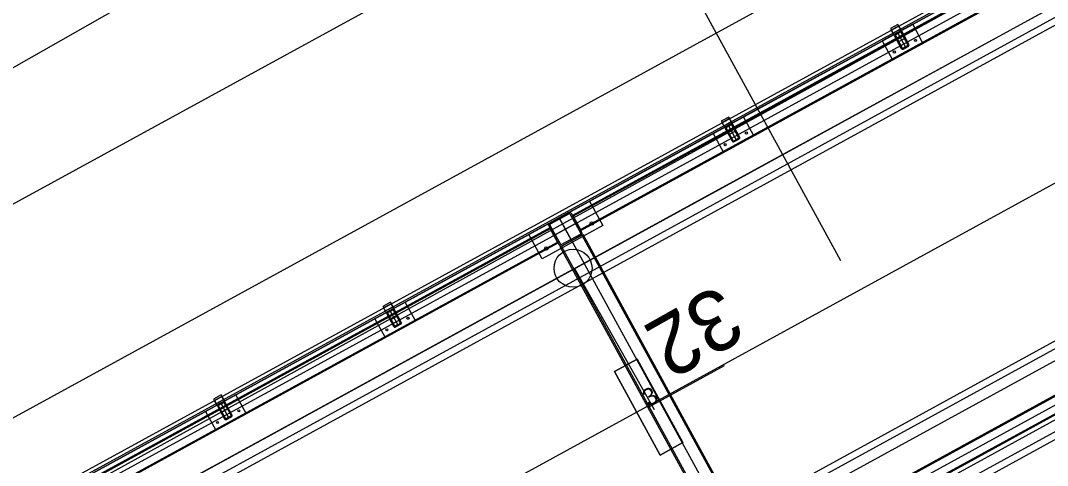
# Model space of a CAD drawing. Extents: x -783978 to -783565, y -1064821 to -1064596.
# Drawn here: x -783747.19 to -783741.25, y -1064670.72 to -1064668.14 of the extents above; entities that cross this region are included whole.
import ezdxf

# ---------------------------------------------------------------- set-up
doc = ezdxf.new("R2010")
doc.units = 0
for name, color, linetype in [('Default', 7, 'Continuous'), ('SO 01_11_01', 7, 'Continuous'), ('SO 01_20_01', 7, 'Continuous'), ('SO 01_50_01', 7, 'Continuous'), ('SO 01_74_01', 7, 'Continuous'), ('SO 01_86_04', 7, 'Continuous')]:
    doc.layers.add(name, color=color, linetype=linetype)

# ---------------------------------------------------------------- blocks, each defined once
blk = doc.blocks.new('POINT_DISPLAY')
at = {"layer": 'Default'}
blk.add_line((0, 0), (0, 0), dxfattribs=at)

msp = doc.modelspace()

# ---------------------------------------------------------------- linework, layer by layer
at = {"layer": 'SO 01_11_01'}
for p, q in [((-783772.8819, -1064683.2217), (-783730.898, -1064660.279)), ((-783749.059, -1064669.4549), (-783743.8421, -1064666.4911))]:
    msp.add_line(p, q, dxfattribs=at)
at = {"layer": 'SO 01_20_01'}
for p, q in [((-783735.0054, -1064663.7532), (-783787.4671, -1064692.4555)), ((-783735.2041, -1064664.4318), (-783786.7885, -1064692.6541)), ((-783786.6445, -1064692.9173), (-783735.3233, -1064664.839)), ((-783738.0171, -1064666.3812), (-783786.4402, -1064692.874)), ((-783786.421, -1064692.9091), (-783737.9979, -1064666.4163)), ((-783737.8741, -1064667.2605), (-783785.3352, -1064693.2269)), ((-783785.6531, -1064694.3127), (-783737.23, -1064667.82)), ((-783737.0912, -1064667.858), (-783785.7805, -1064694.4964)), ((-783737.2108, -1064667.855), (-783785.6339, -1064694.3478)), ((-783785.6366, -1064694.7596), (-783736.9472, -1064668.1212)), ((-783737.0092, -1064668.2235), (-783746.0685, -1064673.1799)), ((-783746.0493, -1064673.215), (-783736.99, -1064668.2586))]:
    msp.add_line(p, q, dxfattribs=at)
at = {"layer": 'SO 01_50_01'}
for p, q in [((-783786.7885, -1064692.6541), (-783725.4827, -1064659.1131)), ((-783742.9243, -1064668.6556), (-783738.5378, -1064666.2557)), ((-783742.9242, -1064668.6557), (-783738.5378, -1064666.2558)), ((-783742.9242, -1064668.6557), (-783738.5378, -1064666.2558)), ((-783742.4443, -1064669.5329), (-783743.4042, -1064667.7783)), ((-783747.3107, -1064671.0555), (-783742.9243, -1064668.6556)), ((-783747.3106, -1064671.0555), (-783742.9242, -1064668.6557)), ((-783747.3106, -1064671.0555), (-783742.9242, -1064668.6557))]:
    msp.add_line(p, q, dxfattribs=at)
at = {"layer": 'SO 01_74_01'}
for p, q in [((-783735.2185, -1064664.4055), (-783786.6099, -1064692.5222)), ((-783786.6003, -1064692.5398), (-783735.2089, -1064664.423)), ((-783741.1927, -1064667.7368), (-783743.9955, -1064669.2702)), ((-783741.1897, -1064667.7423), (-783743.9925, -1064669.2757)), ((-783743.9505, -1064669.3524), (-783741.1477, -1064667.819)), ((-783743.9475, -1064669.3579), (-783741.1447, -1064667.8245)), ((-783742.1144, -1064668.1669), (-783742.1582, -1064668.1909)), ((-783742.1582, -1064668.1909), (-783742.139, -1064668.226)), ((-783742.1096, -1064668.1757), (-783742.1534, -1064668.1997)), ((-783742.0952, -1064668.202), (-783742.1144, -1064668.1669)), ((-783742.1, -1064668.1932), (-783742.1096, -1064668.1757)), ((-783742.1534, -1064668.1997), (-783742.1438, -1064668.2172)), ((-783742.1438, -1064668.2172), (-783742.1, -1064668.1932)), ((-783742.139, -1064668.226), (-783742.0952, -1064668.202)), ((-783743.0925, -1064668.7021), (-783743.1364, -1064668.7261)), ((-783743.1364, -1064668.7261), (-783743.1172, -1064668.7612)), ((-783743.0877, -1064668.7108), (-783743.1316, -1064668.7348)), ((-783743.0733, -1064668.7372), (-783743.0925, -1064668.7021)), ((-783743.0781, -1064668.7284), (-783743.0877, -1064668.7108)), ((-783743.1316, -1064668.7348), (-783743.122, -1064668.7524)), ((-783743.122, -1064668.7524), (-783743.0781, -1064668.7284)), ((-783743.1172, -1064668.7612), (-783743.0733, -1064668.7372)), ((-783743.9955, -1064669.2702), (-783743.9475, -1064669.3579)), ((-783743.9925, -1064669.2757), (-783743.9505, -1064669.3524)), ((-783744.1272, -1064669.3423), (-783746.93, -1064670.8757)), ((-783744.1242, -1064669.3478), (-783746.927, -1064670.8812)), ((-783744.0792, -1064669.43), (-783744.1272, -1064669.3423)), ((-783744.0823, -1064669.4245), (-783744.1242, -1064669.3478)), ((-783746.8851, -1064670.9579), (-783744.0823, -1064669.4245)), ((-783746.882, -1064670.9634), (-783744.0792, -1064669.43)), ((-783744.0672, -1064669.4519), (-783743.9357, -1064669.3799)), ((-783744.0602, -1064669.4481), (-783743.9427, -1064669.3838)), ((-783743.9427, -1064669.3838), (-783741.9268, -1064673.0684)), ((-783743.9357, -1064669.3799), (-783741.9198, -1064673.0645)), ((-783742.0514, -1064673.1365), (-783744.0672, -1064669.4519)), ((-783742.0443, -1064673.1327), (-783744.0602, -1064669.4481)), ((-783740.1128, -1064669.7106), (-783742.9156, -1064671.2441)), ((-783740.1098, -1064669.7162), (-783742.9126, -1064671.2496)), ((-783745.0489, -1064669.7724), (-783745.0927, -1064669.7964)), ((-783745.0441, -1064669.7812), (-783745.0879, -1064669.8052)), ((-783745.0297, -1064669.8075), (-783745.0489, -1064669.7724)), ((-783745.0345, -1064669.7987), (-783745.0441, -1064669.7812)), ((-783742.8706, -1064671.3263), (-783740.0678, -1064669.7928)), ((-783745.0927, -1064669.7964), (-783745.0735, -1064669.8315)), ((-783745.0879, -1064669.8052), (-783745.0783, -1064669.8227)), ((-783745.0783, -1064669.8227), (-783745.0345, -1064669.7987)), ((-783745.0735, -1064669.8315), (-783745.0297, -1064669.8075)), ((-783742.8676, -1064671.3318), (-783740.0648, -1064669.7984)), ((-783746.0271, -1064670.3076), (-783746.0709, -1064670.3316)), ((-783746.0223, -1064670.3163), (-783746.0661, -1064670.3403)), ((-783746.0079, -1064670.3427), (-783746.0271, -1064670.3076)), ((-783746.0127, -1064670.3339), (-783746.0223, -1064670.3163)), ((-783746.0709, -1064670.3316), (-783746.0517, -1064670.3667)), ((-783746.0661, -1064670.3403), (-783746.0565, -1064670.3579)), ((-783746.0565, -1064670.3579), (-783746.0127, -1064670.3339)), ((-783746.0517, -1064670.3667), (-783746.0079, -1064670.3427))]:
    msp.add_line(p, q, dxfattribs=at)
for points in [[(-783735.1681, -1064664.4976), (-783787.4762, -1064693.1159)], [(-783734.0882, -1064666.4715), (-783786.3963, -1064695.0898)], [(-783742.1345, -1064668.2343), (-783742.0956, -1064668.3054)], [(-783742.1035, -1064668.2065), (-783742.1307, -1064668.2215)], [(-783742.129, -1064668.2313), (-783742.09, -1064668.3024)], [(-783742.1004, -1064668.2121), (-783742.1277, -1064668.227)], [(-783742.1171, -1064668.214), (-783742.0691, -1064668.3017)], [(-783742.0712, -1064668.2459), (-783742.115, -1064668.2699)], [(-783742.0572, -1064668.2845), (-783742.0962, -1064668.2133)], [(-783742.0517, -1064668.2814), (-783742.0906, -1064668.2103)], [(-783742.0858, -1064668.3037), (-783742.0585, -1064668.2887)], [(-783742.0827, -1064668.3092), (-783742.0555, -1064668.2943)], [(-783743.1127, -1064668.7694), (-783743.0737, -1064668.8406)], [(-783743.0816, -1064668.7417), (-783743.1089, -1064668.7566)], [(-783743.1071, -1064668.7664), (-783743.0682, -1064668.8376)], [(-783743.0786, -1064668.7472), (-783743.1059, -1064668.7621)], [(-783743.0953, -1064668.7492), (-783743.0473, -1064668.8369)], [(-783743.0493, -1064668.781), (-783743.0932, -1064668.805)], [(-783743.0354, -1064668.8196), (-783743.0743, -1064668.7485)], [(-783743.0299, -1064668.8166), (-783743.0688, -1064668.7454)], [(-783743.0639, -1064668.8388), (-783743.0367, -1064668.8239)], [(-783743.0609, -1064668.8444), (-783743.0336, -1064668.8294)], [(-783744.0182, -1064669.2541), (-783744.1287, -1064669.3146)], [(-783743.9414, -1064669.3694), (-783744.0019, -1064669.2589)], [(-783744.0143, -1064669.2611), (-783744.1249, -1064669.3216)], [(-783743.9716, -1064669.3141), (-783744.1032, -1064669.3861)], [(-783744.0734, -1064669.2843), (-783741.9136, -1064673.2321)], [(-783744.0014, -1064669.4159), (-783744.0734, -1064669.2843)], [(-783743.9484, -1064669.3732), (-783744.0089, -1064669.2627)], [(-783744.1335, -1064669.3309), (-783744.073, -1064669.4414)], [(-783744.1265, -1064669.327), (-783744.066, -1064669.4375)], [(-783744.0606, -1064669.4391), (-783743.95, -1064669.3787)], [(-783744.0567, -1064669.4462), (-783743.9462, -1064669.3857)], [(-783745.069, -1064669.8398), (-783745.0301, -1064669.9109)], [(-783745.038, -1064669.812), (-783745.0653, -1064669.827)], [(-783745.0635, -1064669.8368), (-783745.0246, -1064669.9079)], [(-783745.0349, -1064669.8176), (-783745.0622, -1064669.8325)], [(-783745.0516, -1064669.8195), (-783745.0036, -1064669.9072)], [(-783745.0057, -1064669.8514), (-783745.0495, -1064669.8754)], [(-783744.9917, -1064669.89), (-783745.0307, -1064669.8188)], [(-783744.9862, -1064669.8869), (-783745.0251, -1064669.8158)], [(-783745.0203, -1064669.9092), (-783744.993, -1064669.8942)], [(-783745.0173, -1064669.9147), (-783744.99, -1064669.8998)], [(-783746.0472, -1064670.375), (-783746.0083, -1064670.4461)], [(-783746.0161, -1064670.3472), (-783746.0434, -1064670.3621)], [(-783746.0417, -1064670.3719), (-783746.0027, -1064670.4431)], [(-783746.0131, -1064670.3527), (-783746.0404, -1064670.3677)], [(-783746.0298, -1064670.3547), (-783745.9818, -1064670.4424)], [(-783745.9839, -1064670.3865), (-783746.0277, -1064670.4105)], [(-783745.9699, -1064670.4251), (-783746.0088, -1064670.354)], [(-783745.9644, -1064670.4221), (-783746.0033, -1064670.351)], [(-783745.9985, -1064670.4443), (-783745.9712, -1064670.4294)], [(-783745.9954, -1064670.4499), (-783745.9681, -1064670.4349)]]:
    msp.add_lwpolyline(points, dxfattribs=at)
for points in [[(-783742.0294, -1064668.166), (-783742.2048, -1064668.262), (-783742.1472, -1064668.3673), (-783741.9718, -1064668.2713)], [(-783743.0075, -1064668.7012), (-783743.183, -1064668.7972), (-783743.1254, -1064668.9024), (-783742.9499, -1064668.8064)], [(-783743.8212, -1064669.3287), (-783744.1721, -1064669.5207), (-783744.2489, -1064669.3803), (-783743.898, -1064669.1883)], [(-783744.9639, -1064669.7715), (-783745.1393, -1064669.8675), (-783745.0817, -1064669.9728), (-783744.9063, -1064669.8768)], [(-783745.9421, -1064670.3067), (-783746.1175, -1064670.4027), (-783746.0599, -1064670.5079), (-783745.8845, -1064670.4119)]]:
    msp.add_lwpolyline(points, close=True, dxfattribs=at)
for centre, radius in [((-783742.0125, -1064668.2593), 0.006), ((-783742.1353, -1064668.3265), 0.006), ((-783742.9907, -1064668.7945), 0.006), ((-783743.1135, -1064668.8617), 0.006), ((-783743.8843, -1064669.3176), 0.01), ((-783744.1474, -1064669.4616), 0.01), ((-783744.947, -1064669.8649), 0.006), ((-783745.0698, -1064669.932), 0.006), ((-783745.9252, -1064670.4), 0.006), ((-783746.048, -1064670.4672), 0.006)]:
    msp.add_circle(centre, radius, dxfattribs=at)
for centre, radius, start, end in [((-783742.1262, -1064668.2297), 0.00945, 118.68349, 208.68349), ((-783742.1262, -1064668.2297), 0.00315, 118.68349, 208.68349), ((-783742.0989, -1064668.2148), 0.00945, 28.68349, 118.68349), ((-783742.0989, -1064668.2148), 0.00315, 28.68349, 118.68349), ((-783742.0873, -1064668.3009), 0.00945, 208.68349, 298.68349), ((-783742.0873, -1064668.3009), 0.00315, 208.68349, 298.68349), ((-783742.06, -1064668.286), 0.00315, 298.68349, 28.68349), ((-783742.06, -1064668.286), 0.00945, 298.68349, 28.68349), ((-783743.1044, -1064668.7649), 0.00945, 118.68349, 208.68349), ((-783743.1044, -1064668.7649), 0.00315, 118.68349, 208.68349), ((-783743.0771, -1064668.75), 0.00945, 28.68349, 118.68349), ((-783743.0771, -1064668.75), 0.00315, 28.68349, 118.68349), ((-783743.0655, -1064668.8361), 0.00945, 208.68349, 298.68349), ((-783743.0655, -1064668.8361), 0.00315, 208.68349, 298.68349), ((-783743.0382, -1064668.8211), 0.00315, 298.68349, 28.68349), ((-783743.0382, -1064668.8211), 0.00945, 298.68349, 28.68349), ((-783744.0124, -1064669.2646), 0.012, 28.68349, 118.68349), ((-783744.123, -1064669.3251), 0.012, 118.68349, 208.68349), ((-783744.0124, -1064669.2646), 0.004, 28.68349, 118.68349), ((-783744.123, -1064669.3251), 0.004, 118.68349, 208.68349), ((-783743.9519, -1064669.3752), 0.004, 298.68349, 28.68349), ((-783743.9519, -1064669.3752), 0.012, 298.68349, 28.68349), ((-783744.0625, -1064669.4356), 0.004, 208.68349, 298.68349), ((-783744.0625, -1064669.4356), 0.012, 208.68349, 298.68349), ((-783745.0607, -1064669.8352), 0.00945, 118.68349, 208.68349), ((-783745.0607, -1064669.8352), 0.00315, 118.68349, 208.68349), ((-783745.0334, -1064669.8203), 0.00945, 28.68349, 118.68349), ((-783745.0334, -1064669.8203), 0.00315, 28.68349, 118.68349), ((-783745.0218, -1064669.9064), 0.00945, 208.68349, 298.68349), ((-783745.0218, -1064669.9064), 0.00315, 208.68349, 298.68349), ((-783744.9945, -1064669.8915), 0.00315, 298.68349, 28.68349), ((-783744.9945, -1064669.8915), 0.00945, 298.68349, 28.68349), ((-783746.0389, -1064670.3704), 0.00945, 118.68349, 208.68349), ((-783746.0389, -1064670.3704), 0.00315, 118.68349, 208.68349), ((-783746.0116, -1064670.3555), 0.00945, 28.68349, 118.68349), ((-783746.0116, -1064670.3555), 0.00315, 28.68349, 118.68349), ((-783746, -1064670.4416), 0.00945, 208.68349, 298.68349), ((-783746, -1064670.4416), 0.00315, 208.68349, 298.68349), ((-783745.9727, -1064670.4266), 0.00315, 298.68349, 28.68349), ((-783745.9727, -1064670.4266), 0.00945, 298.68349, 28.68349)]:
    msp.add_arc(centre, radius, start, end, dxfattribs=at)
at = {"layer": 'SO 01_86_04'}
for p, q in [((-783743.9837, -1064669.5772), (-783743.5237, -1064670.3916)), ((-783743.6225, -1064670.1006), (-783743.7541, -1064670.1726)), ((-783743.6225, -1064670.1006), (-783743.7541, -1064670.1726)), ((-783743.7541, -1064670.1726), (-783743.6225, -1064670.1006)), ((-783743.7541, -1064670.1726), (-783743.6225, -1064670.1006)), ((-783743.3585, -1064670.5831), (-783743.6225, -1064670.1006)), ((-783743.3585, -1064670.5831), (-783743.6225, -1064670.1006)), ((-783743.6225, -1064670.1006), (-783743.3585, -1064670.5831)), ((-783743.6225, -1064670.1006), (-783743.3585, -1064670.5831)), ((-783743.5563, -1064670.3779), (-783743.1177, -1064670.1379)), ((-783743.7541, -1064670.1726), (-783743.4901, -1064670.6551)), ((-783743.7541, -1064670.1726), (-783743.4901, -1064670.6551)), ((-783743.4901, -1064670.6551), (-783743.7541, -1064670.1726)), ((-783743.4901, -1064670.6551), (-783743.7541, -1064670.1726)), ((-783743.4901, -1064670.6551), (-783743.3585, -1064670.5831)), ((-783743.4901, -1064670.6551), (-783743.3585, -1064670.5831)), ((-783743.3585, -1064670.5831), (-783743.4901, -1064670.6551)), ((-783743.3585, -1064670.5831), (-783743.4901, -1064670.6551))]:
    msp.add_line(p, q, dxfattribs=at)
for points in [[(-783735.4626, -1064664.5844), (-783749.7616, -1064672.4637), (-783749.643, -1064672.6735)], [(-783738.3222, -1064666.4797), (-783740.5325, -1064667.689), (-783743.1715, -1064669.1328), (-783745.7538, -1064670.5456), (-783748.4385, -1064672.0145), (-783751.0413, -1064673.4385), (-783753.6847, -1064674.8847), (-783756.3281, -1064676.3309), (-783758.9715, -1064677.7772), (-783761.6149, -1064679.2234), (-783764.2583, -1064680.6696), (-783766.9018, -1064682.1159), (-783769.4633, -1064683.5173), (-783772.109, -1064684.9648), (-783774.7882, -1064686.4306), (-783778.1382, -1064688.2722), (-783783.8139, -1064691.3971), (-783785.747, -1064692.4898)]]:
    msp.add_lwpolyline(points, dxfattribs=at)
msp.add_circle((-783743.9927, -1064669.5759), 0.1097, dxfattribs=at)

# ---------------------------------------------------------------- block references
at = {"layer": 'SO 01_86_04', "xscale": 0.010000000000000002, "yscale": 0.009999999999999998, "rotation": 28.683491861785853}
for p in [(-783743.6225, -1064670.1006), (-783743.6225, -1064670.1006), (-783743.7541, -1064670.1726), (-783743.7541, -1064670.1726), (-783743.3585, -1064670.5831), (-783743.3585, -1064670.5831), (-783743.4901, -1064670.6551), (-783743.4901, -1064670.6551)]:
    msp.add_blockref('POINT_DISPLAY', p, dxfattribs=at)

# ---------------------------------------------------------------- texts
at = {"layer": 'SO 01_86_04'}
for s, height, rotation, p in [('32', 0.351, 209.46001, (-783743.1478, -1064669.6634)), ('3', 0.1, 28.68349, (-783743.5563, -1064670.3779))]:
    msp.add_text(s, height=height, rotation=rotation, dxfattribs=at).set_placement(p)

doc.saveas('drawing.dxf')
